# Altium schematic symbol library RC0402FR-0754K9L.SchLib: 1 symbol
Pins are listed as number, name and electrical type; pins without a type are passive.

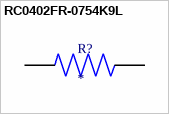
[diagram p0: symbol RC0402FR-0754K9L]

## RC0402FR-0754K9L
designator R?
54.9 kOhms Â±1% 0.063W, 1/16W Chip Resistor 0402 (1005 Metric) Moisture Resistant Thick Film; MF: Yageo; MP: RC0402FR-0754K9L
footprint RESC1005X40N
pins: 1, 2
